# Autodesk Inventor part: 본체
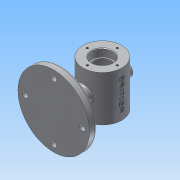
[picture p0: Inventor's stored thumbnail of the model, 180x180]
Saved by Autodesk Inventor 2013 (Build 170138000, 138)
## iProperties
Created: 2018-12
Part Number: 본체
Material: 알루미늄 6061
Document SubType Name: Modeling
Designer: Administrator
Mass: 687.613 g
Surface Area: 555.755 cm^2
Volume: 253.732 cm^3
Density: 2.71 g/cm^3
Author: Administrator
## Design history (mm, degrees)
sketch "스케치1"
  geometry: C1 r 30 at (0, 0); 1 further point
  constraints: 1 centre point, 1 coincident
  dimensions: "d0" = 60 diameter of C1
extrude "돌출1" new body sketch "스케치1" distance "d1" = 35; taper "d2" = 0 deg
hole "구멍1" diameter "d5" = 28; stored, may be unused: countersink angle "d9" = 90 deg, drill point angle "d11" = 0 deg; dims "d3" = 10, "d4" = 10, "d6" = 6, "d7" = 32, "d8" = 12, "d10" = 15
hole "구멍2" diameter "d14" = 50; stored, may be unused: countersink angle "d18" = 90 deg, drill point angle "d20" = 0 deg; dims "d12" = 10, "d13" = 10, "d15" = 6, "d16" = 32, "d17" = 12, "d19" = 20
sketch "스케치2"
  geometry: C1 r 16 at (0, 0) reference; 1 further point
  constraints: 1 vertical alignment
  dimensions: "d21" = 23 distance of C1.centre point (0, 23)
hole "구멍3" sketch "스케치2" at (0, 23) diameter "d22" = 3.242; stored, may be unused: countersink angle "d26" = 90 deg, drill point angle "d28" = 118 deg; dims "d23" = 8, "d24" = 32, "d25" = 12, "d27" = 10
chamfer "모따기1" distance "d32" = 1; stored, may be unused: second distance "d33" = 2, angle "d34" = 45 deg
fillet "모깎기1" dims "d35" = 3
node "작업 평면1"
sketch "스케치3"
  geometry: C1 r 55 at (0, 0); 1 further point
  constraints: 1 centre point, 1 coincident
  dimensions: "d37" = 110 diameter of C1
extrude "돌출2" join sketch "스케치3" distance "d38" = 11; taper "d39" = 0 deg
sketch "스케치4"
  geometry: C1 r 55 at (0, 0) reference; C2 r 55 at (0, 0) reference
extrude "돌출3" join sketch "스케치4" distance "d40" = 15; taper "d41" = -75 deg
sketch "스케치5"
  geometry: C1 r 55 at (0, 0) reference; C2 r 12 at (0, 0)
  constraints: 1 centre point, 1 coincident
  dimensions: "d42" = 24 diameter of C2
extrude "돌출4" join sketch "스케치5" stored distance "d43" = 15; taper "d44" = 0 deg
sketch "스케치6"
  geometry: C1 r 55 at (0, 0) reference; 1 further point
  constraints: 1 vertical alignment
  dimensions: "d45" = 44 distance of C1.centre point (0, 44)
hole "구멍4" sketch "스케치6" at (0, 44) diameter "d46" = 9; stored, may be unused: countersink angle "d50" = 90 deg, drill point angle "d52" = 0 deg; dims "d47" = 8, "d48" = 32, "d49" = 12, "d51" = 10
hole "구멍5" diameter "d55" = 14; stored, may be unused: countersink angle "d59" = 90 deg, drill point angle "d61" = 118 deg; dims "d53" = 10, "d54" = 10, "d56" = 8, "d57" = 32, "d58" = 12, "d60" = 10
node "작업 평면2"
sketch "스케치7"
  geometry: L1 (30, -35)-(-30, -35) reference; C1 r 10 at (0, 0); 1 further point
  constraints: 1 centre point, 1 coincident
  dimensions: "d66" = 20 diameter of C1; "d67" = 35 distance from line of C1.centre L1
extrude "돌출5" join sketch "스케치7" stored distance "d68" = 15; taper "d69" = 0 deg
hole "구멍6" diameter "d72" = 10; stored, may be unused: countersink angle "d76" = 90 deg, drill point angle "d78" = 0 deg; dims "d70" = 10, "d71" = 10, "d73" = 8, "d74" = 32, "d75" = 12, "d77" = 10
fillet "모깎기2" dims "d79" = 3
chamfer "모따기2" distance "d80" = 1; stored, may be unused: second distance "d81" = 2, angle "d82" = 45 deg
node "작업 평면3"
sketch "스케치8"
  geometry: L1 (30, 35)-(-30, 35) reference; L2 (30, -35)-(30, 35) reference; 2 further points
  constraints: 1 other
  dimensions: "d84" = 35 distance from line of point (0, 0) L1; "d85" = 30 distance from line of L2 point (0, 0)
feature "엠보싱1" sketch "스케치8" dims "d86" = 0.5, "d87" = 0
node "솔리드1"
pattern_circular "원형 패턴1" dims angle "d30" = 360 deg
mirror "대칭1"
pattern_circular "원형 패턴2" dims angle "d63" = 360 deg
node "투영된 루프1"
other parameters: "d36" = -75, "d65" = -112, "d83" = 64
